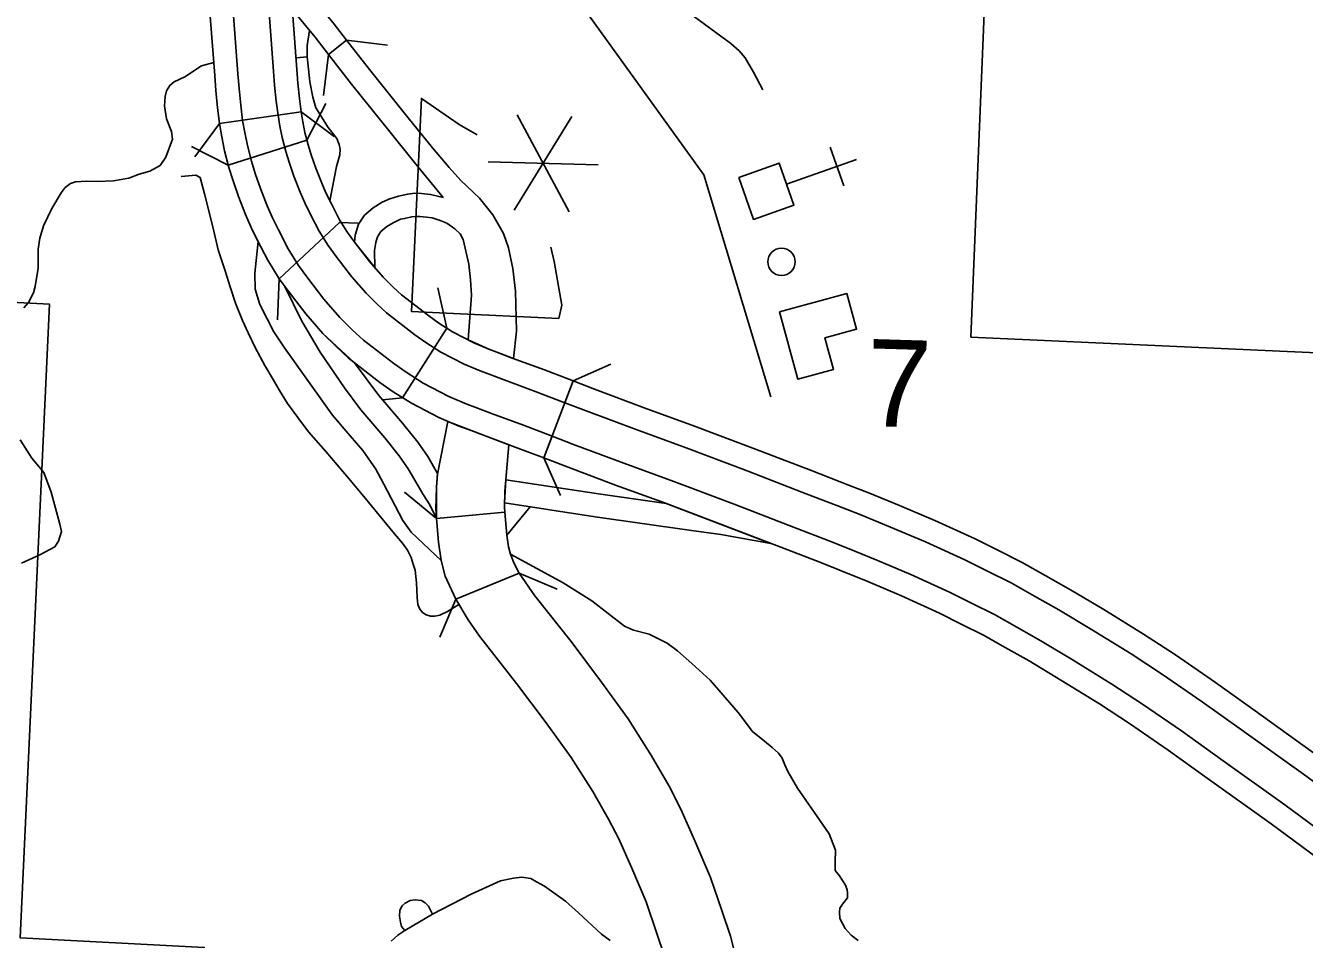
# Model space of a CAD drawing. Extents: x 653372 to 905732, y 627442 to 787275.
# Drawn here: x 657573 to 662227, y 762760 to 766085 of the extents above; entities that cross this region are included whole.
import ezdxf

# ---------------------------------------------------------------- set-up
doc = ezdxf.new("R2010")
doc.units = 0
for name, color, linetype in [('15', 7, 'Continuous'), ('19', 7, 'Continuous'), ('33', 7, 'Continuous'), ('35', 7, 'Continuous'), ('36', 7, 'Continuous'), ('37', 7, 'Continuous'), ('48', 7, 'Continuous'), ('56', 7, 'Continuous'), ('57', 7, 'Continuous'), ('58', 7, 'Continuous'), ('6', 7, 'Continuous')]:
    doc.layers.add(name, color=color, linetype=linetype)

msp = doc.modelspace()

# ---------------------------------------------------------------- linework, layer by layer
at = {"layer": '15'}
msp.add_line((659324.5, 764230.3), (659324.3, 764230.2), dxfattribs=at)
for points in [[(658322.1, 766218.9), (658345.7, 765909.3), (658349.6, 765856.1), (658356, 765794.9), (658362.7, 765739.8), (658370.1, 765695.3), (658379.8, 765647.8), (658394.3, 765591), (658408.6, 765546), (658427.5, 765491.9), (658451.7, 765429.2), (658471, 765385.3), (658492.8, 765341.3), (658528.2, 765272.7), (658565.8, 765211.1), (658599.6, 765165.5), (658658.5, 765089.6), (658716.5, 765022.5), (658761.6, 764977.8), (658802.1, 764940.3), (658912.4, 764854.9), (658957.5, 764823.3), (659019.2, 764784), (659112.8, 764735.3), (659178.9, 764707.3), (659211.8, 764694.9)], [(659259.9, 764815.7), (659227.2, 764828), (659168.3, 764853), (659084.2, 764896.7), (659029.7, 764931.5), (658989.5, 764959.6), (658886.2, 765039.6), (658851.5, 765071.7), (658811.6, 765111.2), (658759.1, 765172), (658703.2, 765244.1), (658673.7, 765283.9), (658641.6, 765336.5), (658608.8, 765400), (658588.9, 765440.2), (658571.9, 765478.8), (658549.5, 765536.8), (658531.9, 765587.2), (658519.3, 765626.8), (658506.5, 765676.9), (658497.9, 765719), (658491.4, 765758.3), (658485.1, 765809.6), (658479.1, 765867.6), (658475.4, 765919), (658451.7, 766228.7)], [(658536.5, 766235.1), (658560.1, 765925.3), (658563.8, 765875), (658569.6, 765819.1), (658575.6, 765770.4), (658581.5, 765734.4), (658589.4, 765696), (658601.1, 765650.2), (658612.6, 765614.1), (658629.3, 765566.2), (658650.5, 765511.3), (658665.9, 765476.2), (658684.7, 765438.3), (658715.7, 765378.2), (658744.3, 765331.4), (658770.9, 765295.5), (658824.9, 765225.9), (658873.8, 765169.3), (658910.3, 765133.1), (658941.2, 765104.5), (659039.9, 765028.1), (659077, 765002.2), (659126.8, 764970.4), (659204.6, 764929.9), (659258.7, 764906.9), (659287.4, 764896.1)], [(659184.3, 764614.5), (659147.3, 764628.3), (659076.5, 764658.4), (658976.6, 764710.4), (658910.3, 764752.6), (658862, 764786.4), (658747.1, 764875.3), (658702.8, 764916.4), (658654.3, 764964.4), (658592.7, 765035.8), (658531.9, 765114.2), (658495.3, 765163.6), (658454.1, 765231), (658416.9, 765302.9), (658394, 765349.3), (658373.1, 765396.8), (658347.7, 765462.6), (658328, 765519.1), (658312.5, 765567.6), (658296.9, 765628.8), (658286.5, 765679.8), (658278.6, 765727.7), (658271.5, 765785.4), (658264.9, 765848.6), (658261, 765903), (658237.3, 766212.5)], [(658740.9, 766031.2), (658691.5, 766094.4), (658608.4, 766195.3)], [(658543.6, 766142), (658626, 766041.8), (658674.6, 765979.5)], [(658674.6, 765979.5), (658740.9, 766031.2), (658824.4, 765924.2), (658965.6, 765748.9), (659053.2, 765639.6), (659113.9, 765567.6), (659156.8, 765521.5)], [(659092.4, 765458.5), (658987.8, 765586.8), (658900.1, 765696.3), (658758.6, 765872), (658674.6, 765979.5)], [(659156.8, 765521.5), (659224.3, 765457.1), (659273.4, 765395.4), (659311.9, 765327.6), (659329.7, 765276.5), (659346.3, 765200.8), (659355.1, 765118.3), (659358.8, 764972.9), (659348.6, 764873.2)], [(658843.3, 765204.5), (658769.8, 765297), (658771.8, 765321.9), (658784.1, 765362.1), (658806.4, 765394.9), (658837.7, 765421), (658870.7, 765441.9), (658898.2, 765453.7), (658929.8, 765463.5), (658963.4, 765471.6), (658989.7, 765474.6), (659013.4, 765473.9), (659046.8, 765470.3), (659092.4, 765458.5)], [(659164.8, 765306.6), (659153.7, 765326.8), (659134.6, 765345.5), (659105.8, 765366.1), (659081.9, 765375), (659052.2, 765385.1), (659031.7, 765387.4), (659007.7, 765390), (658993.1, 765390.5), (658978, 765388.8), (658952.1, 765382.5), (658937, 765379.7), (658910, 765367.4), (658887.3, 765353), (658865.6, 765335), (658854, 765315.8), (658846.8, 765295.1), (658842.6, 765266.6), (658843.3, 765204.5)], [(659348.6, 764873.2), (659258.7, 764906.9), (659183.4, 764941), (659195.4, 765104.3), (659191.8, 765159.4), (659185.7, 765217.1), (659164.8, 765306.6)], [(658769.8, 764857.8), (658654.3, 764964.4), (658592.7, 765035.8), (658515.8, 765134.9), (658578.3, 765009.3), (658644.9, 764896.7), (658732.8, 764766.9), (658793.2, 764686.1), (658879.9, 764585), (658932.8, 764518.9), (658965.2, 764472.3), (658989.3, 764430.6), (659020, 764378.1), (659043.3, 764340.3), (659067.8, 764291.5), (659067.7, 764405), (659072.2, 764454.9)], [(659287.4, 764896.1), (659343.9, 764875), (659460.6, 764831.6), (659565.1, 764791.8), (659534.9, 764712.4)], [(659072.2, 764454.9), (659036.2, 764517.3), (659000.1, 764569.2), (658944.5, 764638.6), (658858.8, 764738.6), (658769.8, 764857.8)], [(659534.9, 764712.4), (659430.6, 764752.1), (659314.1, 764795.4), (659259.9, 764815.7)], [(659211.8, 764694.9), (659268.6, 764673.6), (659384.8, 764630.4), (659488.6, 764590.9)], [(659316.9, 764313.9), (659067.8, 764291.5), (659065.4, 764327.6), (659067.7, 764405), (659071.8, 764453), (659109.6, 764644.3), (659238.9, 764594), (659331.9, 764559.6)], [(659488.6, 764590.9), (659458.3, 764511.5), (659354.9, 764550.9), (659238.9, 764594), (659184.3, 764614.5)], [(659331.9, 764559.6), (659317.4, 764390.5), (659315.6, 764332.3), (659316.9, 764313.9)], [(660285.4, 764200), (659904.2, 764345.6), (659657.8, 764380.3), (659321, 764432.1), (659316.1, 764347.9)], [(659316.1, 764347.9), (659645.6, 764297.1), (659995.8, 764247.9), (660103.2, 764232.6), (660285.4, 764200)], [(659369.4, 764091.9), (659351.3, 764127.7), (659337.6, 764161.4), (659330.4, 764188.2), (659324.3, 764230.2), (659316.9, 764313.9)], [(659067.8, 764291.5), (659075.6, 764205.4), (659084.9, 764138.4), (659100.1, 764081.5), (659138, 763997.3)], [(660159.3, 762690), (660137.9, 762771.3), (660106, 762864.9), (660065.1, 762985.4), (660008.5, 763118.3), (659957.5, 763233.2), (659914.6, 763316.9), (659851.1, 763427.7), (659765.6, 763561.8), (659668.5, 763695.8), (659557.8, 763843.8), (659426.4, 764010.1), (659369.4, 764091.9), (659138, 763997.3)], [(659138, 763997.3), (659183.8, 763922.7), (659224.4, 763862.5), (659359.6, 763691.4), (659467.2, 763547.6), (659558.8, 763421.1), (659637.2, 763298.3), (659694.7, 763197.8), (659731.8, 763125.3), (659779.3, 763018.5), (659831.3, 762896.2), (659869.3, 762784.4), (659898.4, 762699.1)]]:
    msp.add_lwpolyline(points, dxfattribs=at)
at = {"layer": '19'}
for points in [[(659534.9, 764712.4), (659565.1, 764791.8), (659643.1, 764762.1), (659824.2, 764694.3), (660006.5, 764627.6), (660228.6, 764543.6), (660428.7, 764466.4), (660571.7, 764411.8), (660644.1, 764383), (660752.9, 764338.6), (660881.6, 764284.3), (661028.1, 764217), (661111.1, 764175.7), (661199.9, 764131.6), (661286, 764082.8), (661375.8, 764032.1), (661496.7, 763959.7), (661641.5, 763870.3), (661757.2, 763794.6), (661903, 763694.1), (662047.2, 763590.9), (662282, 763423.2), (662616.4, 763175.3)], [(662566.4, 763106.6), (662232, 763354.5), (661997.8, 763521.7), (661854.2, 763624.6), (661709.8, 763724), (661595.9, 763798.5), (661452.5, 763887.1), (661333, 763958.6), (661244.1, 764008.8), (661160, 764056.5), (661073.3, 764099.6), (660991.5, 764140.3), (660847.3, 764206.5), (660720.3, 764260.1), (660612.3, 764304.2), (660540.9, 764332.6), (660398.3, 764387), (660198.2, 764464.2), (659976.9, 764548), (659794.7, 764614.6), (659613.1, 764682.6), (659534.9, 764712.4)], [(662440, 762932.7), (662105.5, 763180.6), (661872.8, 763346.8), (661730.6, 763448.6), (661589.9, 763545.5), (661480.5, 763617.1), (661340.8, 763703.4), (661224.9, 763772.8), (661138.3, 763821.7), (661059, 763866.6), (660977.5, 763907.1), (660898.7, 763946.3), (660760.6, 764009.7), (660637.9, 764061.6), (660532, 764104.7), (660462.8, 764132.3), (660321.3, 764186.3), (660121.5, 764263.3), (659901.9, 764346.5), (659720.1, 764413), (659537.1, 764481.4), (659458.3, 764511.5), (659488.6, 764590.9)], [(659488.6, 764590.9), (659567.1, 764560.9), (659749.6, 764492.7), (659931.6, 764426.1), (660151.8, 764342.7), (660351.7, 764265.6), (660493.7, 764211.5), (660563.8, 764183.6), (660670.5, 764140.1), (660794.9, 764087.5), (660935.4, 764023), (661015.4, 763983.2), (661098.9, 763941.7), (661180.1, 763895.7), (661267.6, 763846.2), (661385, 763776), (661526.1, 763688.8), (661637.3, 763616.1), (661779.5, 763518.2), (661922.2, 763416), (662155.5, 763249.4), (662490, 763001.4)]]:
    msp.add_lwpolyline(points, dxfattribs=at)
at = {"layer": '33'}
for points in [[(660255.7, 765851.2), (660222, 765914.6), (660191.2, 765967.1), (660169.2, 765993), (660138.8, 766019.1), (659989.2, 766130.2), (659785.4, 766280.6), (659700.9, 766343.2), (659682.2, 766359.3), (659669.4, 766375.3), (659663.9, 766389.9), (659656.4, 766420.1), (659608.1, 766646.2), (659565.5, 766906.8), (659561.3, 766965.8), (659566.1, 767005.2), (659574.3, 767038.6), (659588.5, 767071.8), (659612.3, 767107.1), (659650.8, 767149.1), (659713.7, 767204.9), (659754.7, 767244.8)], [(659149.9, 763977.9), (659108, 763952.2), (659079.9, 763940), (659061.8, 763935.5), (659046, 763935.4), (659031.1, 763940.5), (659017.6, 763949), (659007.9, 763961.3), (659000.6, 763978), (658997.9, 764004.3), (658995.5, 764057.3), (658990.7, 764103.7), (658983.8, 764125.1), (658975.5, 764149.5), (658962.3, 764175.6), (658944.3, 764200.8), (658915.3, 764235), (658803.1, 764371.4), (658748, 764437.8), (658665.7, 764534.6), (658602.8, 764606.7), (658563.1, 764658.9), (658526.2, 764709.2), (658497.1, 764756.8), (658473.7, 764796.7), (658443.6, 764847.6), (658408.5, 764913.3), (658382.2, 764966.6), (658361.7, 765011.4), (658336.2, 765074.3), (658317.4, 765134.4), (658298.6, 765192.6), (658274, 765268.4), (658254, 765352.4), (658224.3, 765472.6), (658207.5, 765531.8), (658192.1, 765540.2), (658138.5, 765535.9)], [(658902.7, 762753.5), (658927.3, 762775.7), (658952.8, 762791.9), (659053.2, 762851.4), (659194.5, 762924.5), (659301.5, 762973.2), (659348.7, 762982.7), (659378.8, 762985.8), (659411.6, 762980.9), (659432.2, 762969.2), (659461.7, 762953.4), (659538, 762899.1), (659585.2, 762856.7), (659668.7, 762778.3), (659700, 762755.4)], [(658952.8, 762791.9), (658940.9, 762806.4), (658936.9, 762822.5), (658933, 762844.2), (658935.3, 762865.8), (658943.2, 762881.5), (658953.7, 762891.9), (658972.2, 762901.6), (658991.1, 762903.9), (659013.2, 762901.5), (659027.2, 762893.2), (659039.3, 762880.8), (659053.2, 762851.4)]]:
    msp.add_lwpolyline(points, dxfattribs=at)
at = {"layer": '35'}
for points in [[(658605.8, 766066.4), (658597.8, 766012.6), (658597.8, 765970.8), (658601.7, 765926.2), (658606.9, 765880.3), (658618.2, 765824.5), (658629.2, 765785.4), (658673.4, 765713.9), (658705.6, 765673.4), (658714.4, 765652.3), (658717.2, 765635.1), (658716.3, 765614.5), (658704.6, 765572.4), (658680.3, 765446.8)], [(657583, 765076.6), (657601.5, 765112.2), (657607.4, 765134.7), (657618.7, 765202.4), (657618.7, 765270.5), (657624, 765311.6), (657637.7, 765355.5), (657668.5, 765419.5), (657702.1, 765476.2), (657717.1, 765495.3), (657736.1, 765510.2), (657754.9, 765515.9), (657795.1, 765518.8), (657833.2, 765517.6), (657893.1, 765520), (657948, 765529.6), (657986.2, 765544.2), (658024.7, 765555.4), (658062.4, 765574.9), (658082.9, 765606.3), (658107.5, 765671.5), (658103.2, 765699.5), (658086, 765745.3), (658078.2, 765792), (658080.3, 765827), (658086, 765847.4), (658097.9, 765866.6), (658113.8, 765879.6), (658152.5, 765898), (658212.5, 765938.5), (658257.4, 765950.3)], [(658556.9, 765967.1), (658597.8, 765970.8)], [(658419, 765298.9), (658406.7, 765183.5), (658408.6, 765125), (658425.2, 765069.7), (658451.7, 765017.8), (658475.8, 764970.8), (658514.8, 764912.6), (658689.6, 764667)], [(657566.9, 765057.5), (657583, 765076.6)], [(658689.6, 764667), (658753.5, 764592), (658800.6, 764538.9), (658847.6, 764470.5), (658876.1, 764416.2), (658945.8, 764283.6), (658975.6, 764241.9), (659084.9, 764138.4)], [(657557.6, 764128.1), (657624.5, 764159.1), (657678.9, 764187.7), (657691.9, 764209), (657703.3, 764243.7), (657696.8, 764270.7), (657665.3, 764387.1), (657639.6, 764459), (657595.9, 764510.8), (657552.5, 764577.1)], [(659337.6, 764161.4), (659528.7, 764056.9), (659633.9, 763991), (659751.8, 763899.9), (659785.4, 763884.3), (659842.2, 763870.4), (659908.2, 763838), (659945.1, 763810.1), (659997.2, 763763.5), (660063.5, 763703.1), (660165.9, 763585.6), (660218.6, 763515.8), (660261.3, 763480.4), (660289.8, 763457.7), (660312.4, 763437.5), (660326.4, 763418.8), (660335.4, 763395.4), (660346.9, 763370.7), (660382, 763309.4), (660442.7, 763222.3), (660497.5, 763144), (660520.1, 763084.9), (660518.8, 763042.3), (660519.1, 763010.6), (660534.3, 762990.7), (660546, 762974.5), (660556.4, 762957.2), (660563.2, 762939.9), (660564.1, 762928.9), (660563.6, 762910.7), (660545.8, 762888.1), (660535.7, 762873.8), (660535.2, 762859.2), (660535.8, 762836.1), (660555.3, 762799), (660577.8, 762775.2), (660602.7, 762756.2)]]:
    msp.add_lwpolyline(points, dxfattribs=at)
at = {"layer": '36'}
for p, q in [((658596.1, 765667.5), (658664.9, 765800.8)), ((658575.4, 765770.8), (658278.6, 765727.7)), ((658575.4, 765770.8), (658695.6, 765681)), ((658278.6, 765727.7), (658188.8, 765607.5)), ((658310.3, 765576.2), (658596.1, 765667.5)), ((658310.3, 765576.2), (658177, 765644.9)), ((658714.9, 765367.9), (658495.3, 765163.6)), ((658714.9, 765367.9), (658781.3, 765365.6)), ((658495.3, 765163.6), (658489.8, 765013.7)), ((659105.9, 764983.8), (659073.4, 765130.2)), ((658944.7, 764730.7), (659105.9, 764983.8)), ((659565.1, 764791.8), (659702, 764853.1)), ((659565.1, 764791.8), (659458.3, 764511.5)), ((658944.7, 764730.7), (658871.9, 764723.3)), ((659458.3, 764511.5), (659519.7, 764374.6))]:
    msp.add_line(p, q, dxfattribs=at)
at = {"layer": '37'}
for points in [[(658740.9, 766031.2), (658889.7, 766012.9)], [(658656.3, 765830.7), (658674.6, 765979.5)], [(659067.8, 764291.5), (658951.7, 764386.5)], [(659408.9, 764333.6), (659324.3, 764230.2)], [(659369.4, 764091.9), (659507.7, 764033.9)], [(659080, 763859), (659138, 763997.3)]]:
    msp.add_lwpolyline(points, dxfattribs=at)
at = {"layer": '48'}
for p, q in [((659561.1, 765753.6), (659350.8, 765413.3)), ((659361.2, 765759.6), (659550.7, 765407.3)), ((659256.1, 765589.4), (659655.9, 765577.4))]:
    msp.add_line(p, q, dxfattribs=at)
at = {"layer": '56'}
msp.add_circle((660323.6, 765225.1), 50, dxfattribs=at)
at = {"layer": '57'}
for p, q in [((660500.7, 765642.7), (660550.5, 765501.3)), ((660596.3, 765596.9), (660342.4, 765507.4))]:
    msp.add_line(p, q, dxfattribs=at)
msp.add_lwpolyline([(659267.2, 766616.3), (660041.2, 765542.1), (660285, 764734.3)], dxfattribs=at)
msp.add_lwpolyline([(660168.2, 765532.1), (660315.4, 765584), (660369.2, 765431.4), (660222, 765379.5)], close=True, dxfattribs=at)
at = {"layer": '58'}
msp.add_lwpolyline([(660316.7, 765043.1), (660383.2, 764798), (660512.5, 764833), (660481.1, 764949), (660596.9, 764980.4), (660561.9, 765109.6)], close=True, dxfattribs=at)
at = {"layer": '6'}
for points in [[(659814.6, 768224), (659944.8, 767600), (659979.5, 767248.6), (659995.2, 767175.9), (660182, 766834.1), (660710.6, 766294.9), (661067.8, 766277.7), (661012.9, 764951.1), (662351.5, 764890.2), (662383.8, 765662.7)], [(659216.2, 765686.7), (659150.8, 765725.2), (659013.5, 765819.3), (658995.4, 765432.4), (658977.3, 765043.8), (659513.3, 765019.4), (659524.6, 765067), (659516.8, 765108.1), (659496.2, 765225.7), (659484.5, 765277.8)], [(656702.3, 758523.5), (656736.5, 759292.7), (656693.9, 759281.6), (656713.9, 759448), (656741.7, 759439.9), (656754.5, 759815.7), (657408.7, 759782.1), (657469, 761126), (657073.7, 761145.7), (657257, 761638), (657490.9, 761587.3), (657542.4, 762537.2), (658194.6, 762543.4), (658222.8, 762730.3), (657552.4, 762765.5), (657660.1, 765070.5), (656796, 765115.8)]]:
    msp.add_lwpolyline(points, dxfattribs=at)

# ---------------------------------------------------------------- texts
at = {"layer": '58'}
msp.add_text('7', height=316.8, rotation=358.28, dxfattribs=at).set_placement((660628.3, 764628.1))

doc.saveas('drawing.dxf')
